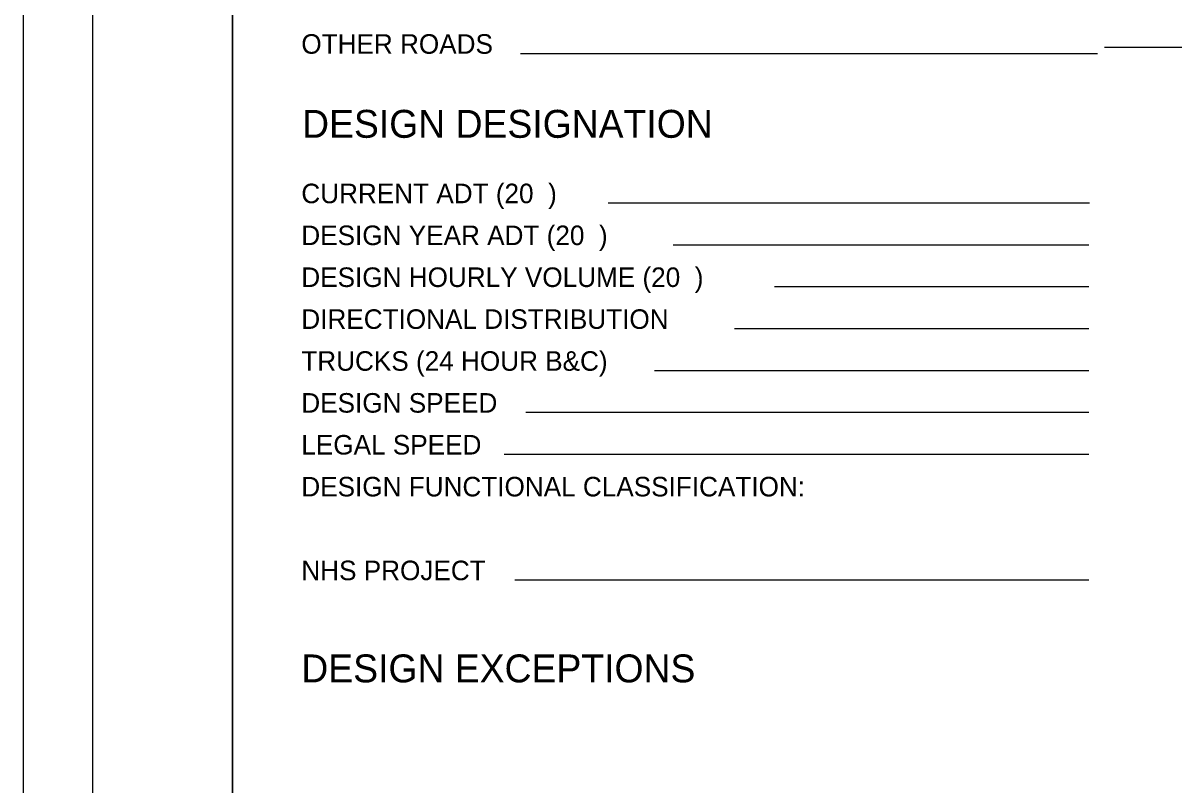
# Model space of a CAD drawing. Extents: x 0 to 34, y 0 to 22.
# Drawn here: x 0 to 8.25, y 5.64 to 11.1 of the extents above; entities that cross this region are included whole.
import ezdxf

# ---------------------------------------------------------------- set-up
doc = ezdxf.new("R2010")
doc.units = 0
for name, color, linetype in [('SH_Border', 7, 'Continuous'), ('SH_Cut_Line', 7, 'Continuous'), ('SH_Data', 7, 'Continuous'), ('SH_Text', 7, 'Continuous')]:
    doc.layers.add(name, color=color, linetype=linetype)

msp = doc.modelspace()

# ---------------------------------------------------------------- linework, layer by layer
at = {"layer": 'SH_Border'}
for points in [[(0.5, 21.5), (1.5, 21.5), (1.5, 0.5), (0.5, 0.5)], [(1.5, 21.5), (33.5, 21.5), (33.5, 0.5), (1.5, 0.5)]]:
    msp.add_lwpolyline(points, close=True, dxfattribs=at)
at = {"layer": 'SH_Cut_Line'}
msp.add_lwpolyline([(0, 0), (34, 0), (34, 22), (0, 22)], close=True, dxfattribs=at)
at = {"layer": 'SH_Data'}
for p, q in [((9, 10.9223), (7.75, 10.9223)), ((7.7, 10.8767), (3.5657, 10.8767)), ((7.6424, 9.8062), (4.1936, 9.8062)), ((7.6368, 9.5062), (4.6592, 9.5062)), ((7.6368, 9.2062), (5.3852, 9.2062)), ((7.6368, 8.9062), (5.0988, 8.9062)), ((7.6368, 8.6062), (4.5259, 8.6062)), ((7.6368, 8.3062), (3.6035, 8.3062)), ((7.6368, 8.0062), (3.4488, 8.0062)), ((7.6368, 7.1062), (3.5243, 7.1062))]:
    msp.add_line(p, q, dxfattribs=at)

# ---------------------------------------------------------------- texts
msp.add_text('DESIGN DESIGNATION', height=0.2, dxfattribs=at).set_placement((2, 10.2747))
at = {"layer": 'SH_Text'}
for s, height, p in [('OTHER ROADS', 0.14, (1.9944, 10.8767)), ('CURRENT ADT (20  )', 0.14, (1.9944, 9.8062)), ('DESIGN YEAR ADT (20  )', 0.14, (1.9944, 9.5062)), ('DESIGN HOURLY VOLUME (20  )', 0.14, (1.9944, 9.2062)), ('DIRECTIONAL DISTRIBUTION', 0.14, (1.9944, 8.9062)), ('TRUCKS (24 HOUR B&C)', 0.14, (1.9944, 8.6062)), ('DESIGN SPEED', 0.14, (1.9944, 8.3062)), ('LEGAL SPEED', 0.14, (1.9944, 8.0062)), ('DESIGN FUNCTIONAL CLASSIFICATION:', 0.14, (1.9944, 7.7062)), ('NHS PROJECT', 0.14, (1.9944, 7.1062)), ('DESIGN EXCEPTIONS', 0.2, (1.9944, 6.3744))]:
    msp.add_text(s, height=height, dxfattribs=at).set_placement(p)

doc.saveas('drawing.dxf')
